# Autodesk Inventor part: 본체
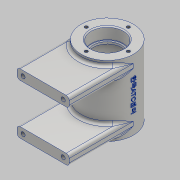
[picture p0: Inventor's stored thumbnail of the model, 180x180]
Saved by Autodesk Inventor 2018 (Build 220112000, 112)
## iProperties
Created: 2020-07
Part Number: 본체
Material: 알루미늄 6061
Document SubType Name: Modeling
Designer: home
Density: 2.7 g/cm^3
Appearance: 알루미늄 - 평지
Mass: 305.238 g
Surface Area: 357.832 cm^2
Volume: 113.051 cm^3
Author: home
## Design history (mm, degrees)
sketch "스케치1"
  geometry: L1 (16, 35)-(26, 35); L2 (26, 35)-(26, -35); L3 (26, -35)-(16, -35); L4 (16, -35)-(16, -23); L5 (16, -23)-(14, -23); L6 (14, -23)-(14, -21); L7 (21, -21)-(14, -21); L8 (21, -21)-(21, 21); L9 (21, 21)-(14, 21); L10 (14, 21)-(14, 23); L11 (14, 23)-(16, 23); L12 (16, 23)-(16, 35); L13 (0, 76.964)-(0, -76.964); 3 further points
  constraints: 26 end point, 9 perpendicular, 2 midpoint, 2 vertical, 1 coincident, 1 horizontal
  dimensions: "d4" = 10 distance of L1.start L1.end; "d5" = 70 distance of L1.end L2.end; "d6" = 10 distance of L2.end L3.end; "d7" = 12 distance of L3.end L4.end; "d8" = 2 distance of L4.end L5.end; "d9" = 2 distance of L5.end L6.end; "d10" = 42 distance of L7.start L8.end; "d11" = 2 distance of L9.end L10.end; "d12" = 2 distance of L10.end L11.end; "d19" = 35 distance from line of point (0, 0) L1; "d20" = 52 diameter of L2 L13; "d21" = 32 diameter of L12 L13 (derived); "d22" = 42 diameter of L8 L13; "d23" = 111.96433 distance from line of L13.start L3
revolve "회전2" sketch "스케치1" stored, may be unused: angle "d24" = 90 deg
node "작업 평면1"
sketch "스케치2"
  geometry: L1 (0, 0)-(0, 20); L2 (0, 0)-(0, -20); L3 (0, 20)-(26, 20); L4 (26, 20)-(26, 30); L5 (26, 30)-(-26, 30); L6 (-26, 30)-(-26, 20); L7 (0, 20)-(-26, 20)
  constraints: 14 end point, 2 horizontal, 2 perpendicular, 2 vertical, 1 point on line
  dimensions: "d26" = 20 distance of L1.start L1.end; "d27" = 20 distance of L1.start L2.end; "d28" = 26 distance of L1.end L3.end; "d29" = 10 distance of L3.end L4.end; "d30" = 52 distance of L4.end L5.end; "d31" = 10 distance of L5.end L6.end
extrude "돌출1" join sketch "스케치2" stored distance "d32" = 10; taper "d33" = 0 deg
sketch "스케치3"
  geometry: L1 (-26, 20)-(26, 20) reference; L2 (0, 20)-(0, 25); L3 (0, 25)-(20, 25); L4 (0, 25)-(-20, 25); 3 further points
  constraints: 6 end point, 2 coincident, 1 horizontal, 1 midpoint, 1 perpendicular, 1 vertical
  dimensions: "d34" = 5 distance of L2.start L2.end; "d35" = 20 distance of L2.end L3.end; "d36" = 20 distance of L2.end L4.end
hole "구멍1" sketch "스케치3" at (20, 25), (-20, 25) diameter "d37" = 4.134; stored, may be unused: countersink angle "d41" = 90 deg, drill point angle "d43" = 118 deg; dims "d38" = 8, "d39" = 4, "d40" = 2, "d42" = 10
sketch "스케치4"
  geometry: C1 r 21 at (0, 0); 3 further points
  constraints: 1 centre point, 1 coincident, 1 vertical alignment, 2 other
  dimensions: "d44" = 42 diameter of C1
hole "구멍2" sketch "스케치4" at (0, 21) diameter "d45" = 3.242; stored, may be unused: countersink angle "d49" = 90 deg, drill point angle "d51" = 118 deg; dims "d46" = 8, "d47" = 4, "d48" = 2, "d50" = 10
node "작업 평면2"
sketch "스케치5"
  geometry: C1 r 5 at (0, 0); 1 further point
  constraints: 1 centre point, 1 coincident
  dimensions: "d56" = 10 diameter of C1
extrude "돌출2" join sketch "스케치5" stored distance "d57" = 10; taper "d58" = 0 deg
sketch "스케치6"
  geometry: L1 (0, 0)-(0, -40.46); L2 (0, 0)-(-9.919, -27.251); 1 further point
  constraints: 4 end point, 1 coincident, 1 vertical
  dimensions: "d85" = 29 distance of L1.start L2.end; "d86" = 20 deg angle of L1 L2; "d87" = 13.83811 distance from line of L1.end L2
sketch "스케치8"
  geometry: 2 further points
  constraints: 1 coincident
hole "구멍3" sketch "스케치8" at (0, 0) diameter "d65" = 5.188; stored, may be unused: countersink angle "d69" = 90 deg, drill point angle "d71" = 118 deg; dims "d66" = 20, "d67" = 4, "d68" = 2, "d70" = 20
chamfer "모따기1" distance "d82" = 1; stored, may be unused: second distance "d83" = 2, angle "d84" = 45 deg
node "작업 평면4"
sketch "스케치10"
  geometry: C1 r 6 at (0, 0); 1 further point
  constraints: 1 centre point, 1 coincident
  dimensions: "d88" = 12 diameter of C1
extrude "돌출4" join sketch "스케치10" stored distance "d89" = 10; taper "d90" = 0 deg
sketch "스케치11"
  geometry: 2 further points
  constraints: 1 coincident
hole "구멍5" sketch "스케치11" at (0, 0) diameter "d91" = 5.188; stored, may be unused: countersink angle "d95" = 90 deg, drill point angle "d97" = 118 deg; dims "d92" = 20, "d93" = 4, "d94" = 2, "d96" = 20
fillet "모깎기1" dims "d79" = 3, "d80" = 2, "d81" = 3, "d103" = 0.3
node "작업 평면5"
sketch "스케치12"
  geometry: L1 (-26, 35)-(26, 35) reference; L2 (29, 5)-(29, -5) reference; 2 further points
  constraints: 1 other
  dimensions: "d99" = 35 distance from line of L1 point (0, 0); "d100" = 29 distance from line of L2 point (0, 0)
feature "엠보싱1" sketch "스케치12" dims "d4" = 10, "d5" = 70, "d6" = 10, "d7" = 12, "d8" = 2, "d9" = 2, "d10" = 42, "d11" = 2, "d12" = 2, "d19" = 35, "d20" = 52, "d21" = 32 (derived), "d22" = 42, "d23" = 111.96433, "d26" = 20, "d28" = 26, "d29" = 10, "d30" = 52, "d31" = 10, "d101" = 0.5, "d102" = 0
node "솔리드2"
pattern_circular "원형 패턴1" dims angle "d53" = 360 deg
mirror "미러1"
other parameters: "d25" = -64, "d55" = 29, "d98" = 26
